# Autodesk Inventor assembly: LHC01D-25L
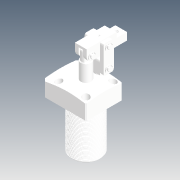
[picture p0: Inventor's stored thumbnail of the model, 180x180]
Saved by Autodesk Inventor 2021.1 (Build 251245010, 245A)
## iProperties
Created: 2019-04
Part Number: LHC01D-25L
Description: STEP AP214
Document SubType Name: Assembly
Designer: user
Title: LHC01D-25L.STEP
Revision Number: ÈÎºÎ
Sending System: SolidWorks 2016
Preprocessor: SwSTEP 2.0
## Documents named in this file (12)
- D:\Vault_2016\Projekty\Clamptek\Hydraulic\LHC01D\Inventor\LHC01D-25L\LHC01D-25L.iam
- D:\Vault_2016\Projekty\Clamptek\Hydraulic\LHC01D\Inventor\LHC01D-25L\LHC01D-25-01_1.ipt
- D:\Vault_2016\Projekty\Clamptek\Hydraulic\LHC01D\Inventor\LHC01D-25L\CPLCU-25-01_1.ipt
- D:\Vault_2016\Projekty\Clamptek\Hydraulic\LHC01D\Inventor\LHC01D-25L\CPLCU-25-02_1.ipt
- D:\Vault_2016\Projekty\Clamptek\Hydraulic\LHC01D\Inventor\LHC01D-25L\CPLCU-25-03_1.ipt
- D:\Vault_2016\Projekty\Clamptek\Hydraulic\LHC01D\Inventor\LHC01D-25L\CPLCU-25-04_1.ipt
- D:\Vault_2016\Projekty\Clamptek\Hydraulic\LHC01D\Inventor\LHC01D-25L\CPLCU-25-05_1.ipt
- D:\Vault_2016\Projekty\Clamptek\Hydraulic\LHC01D\Inventor\LHC01D-25L\LHC01D25»îÈû¸Ë.ipt
- D:\Vault_2016\Projekty\Clamptek\Hydraulic\LHC01D\Inventor\LHC01D-25L\CPLCU-25-09_1.ipt
- D:\Vault_2016\Projekty\Clamptek\Hydraulic\LHC01D\Inventor\LHC01D-25L\LHC01D-32-01_1.ipt
- D:\Vault_2016\Projekty\Clamptek\Hydraulic\LHC01D\Inventor\LHC01D-25L\M4ningjin_1.ipt
- D:\Vault_2016\Projekty\Clamptek\Hydraulic\LHC01D\Inventor\LHC01D-25L\¶ÂÍ·_1.ipt
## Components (24 placed, 24 different names)
1. LHC01D-25-01_1_1
2. CPLCU-25-01_1_2
3. CPLCU-25-02_1_3
4. CPLCU-25-03_1_4
5. CPLCU-25-04_1_5
6. CPLCU-25-05_1_6
7. LHC01D25»îÈû¸Ë_7
8. CPLCU-25-09_1_8
9. LHC01D-32-01_1_9
10. CPLCU-25-02_1_10
11. CPLCU-25-09_1_11
12. CPLCU-25-09_1_12
13. CPLCU-25-09_1_13
14. CPLCU-25-09_1_14
15. CPLCU-25-09_1_15
16. LHC01D-32-01_1_16
17. LHC01D-32-01_1_17
18. LHC01D-32-01_1_18
19. LHC01D-32-01_1_19
20. LHC01D-32-01_1_20
21. CPLCU-25-04_1_21
22. M4ningjin_1_22
23. ¶ÂÍ·_1_23
24. ¶ÂÍ·_1_24
